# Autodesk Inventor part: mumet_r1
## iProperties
Shininess: 64.0
Length Units: 11269
Angle Units: 11279
Time Units: 11290
Mass Units: 11283
Length Display Precision: 3
Angle Display Precision: 2
Compacted: True
Part Number: mumet_r1
Document SubType Name: Modeling
Created: 2004-07
Designer: Peter
Manufacturer: Standard
Standards Organization: Custom
Density: 0.0
Volumn: 0.0
Area: 0.0
PropertySet Name: Model Information
Control State: 0
Master: False
Checked Out: False
Author: Peter
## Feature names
1. Revolution2
